(* LS Electric XG5000 project: test *)
(* PLC NewPLC *)
(* module base 0 slot 3: Output Module:XBE-TN/TP32A (Transistor Output, 32 Contacts (0.2A, Sink Output/Source Output)) *)

PROGRAM forvup (* task: Scan Program *)
VAR
    dummy : DWORD;
    fromvup AT D01006 : DWORD;
    mysign1 AT D01000 : DWORD;
    mysign2 AT D01002 : DWORD;
    tovup AT D01004 : DWORD;
    _p100 AT P00100 : BIT;
    _p101 AT P00101 : BIT;
    _p102 AT P00102 : BIT;
    _p103 AT P00103 : BIT;
    _p104 AT P00104 : BIT;
    _p105 AT P00105 : BIT;
    _p106 AT P00106 : BIT;
    _p107 AT P00107 : BIT;
    _p108 AT P00108 : BIT;
    _p109 AT P00109 : BIT;
    _p110 AT P00110 : BIT;
    _p111 AT P00111 : BIT;
    _p120 AT P00120 : BIT;
    _p121 AT P00121 : BIT;
    _p122 AT P00122 : BIT;
    _p123 AT P00123 : BIT;
    _p124 AT P00124 : BIT;
    _p125 AT P00125 : BIT;
    _p126 AT P00126 : BIT;
    _p127 AT P00127 : BIT;
    _p128 AT P00128 : BIT;
    _p129 AT P00129 : BIT;
    _p130 AT P00130 : BIT;
    _p131 AT P00131 : BIT;
    _p132 AT P00132 : BIT;
    _p133 AT P00133 : BIT;
    _p134 AT P00134 : BIT;
    _p135 AT P00135 : BIT;
    _p136 AT P00136 : BIT;
    _p137 AT P00137 : BIT;
    _p138 AT P00138 : BIT;
    _p139 AT P00139 : BIT;
    _p140 AT P00140 : BIT;
    _p141 AT P00141 : BIT;
    _p142 AT P00142 : BIT;
    _p143 AT P00143 : BIT;
    _p144 AT P00144 : BIT;
    _p145 AT P00145 : BIT;
    _p146 AT P00146 : BIT;
    _p147 AT P00147 : BIT;
    _p148 AT P00148 : BIT;
    _p149 AT P00149 : BIT;
    _p150 AT P00150 : BIT;
    _p151 AT P00151 : BIT;
    _p80 AT P00080 : BIT;
    _p81 AT P00081 : BIT;
    _p82 AT P00082 : BIT;
    _p83 AT P00083 : BIT;
    _p84 AT P00084 : BIT;
    _p85 AT P00085 : BIT;
    _p86 AT P00086 : BIT;
    _p87 AT P00087 : BIT;
    _p88 AT P00088 : BIT;
    _p89 AT P00089 : BIT;
    _p90 AT P00090 : BIT;
    _p91 AT P00091 : BIT;
    _p92 AT P00092 : BIT;
    _p93 AT P00093 : BIT;
    _p94 AT P00094 : BIT;
    _p95 AT P00095 : BIT;
    _p96 AT P00096 : BIT;
    _p97 AT P00097 : BIT;
    _p98 AT P00098 : BIT;
    _p99 AT P00099 : BIT;
END_VAR
(* sign *)
mysign1:=1380534594;
mysign2:=1432778632;
(* copy from vup to XGSIM inputs*)
IF (fromvup AND 1) =0 THEN
_p80:=FALSE;	
ELSE
_p80:=TRUE;	
END_IF;
IF (fromvup AND 2) =0 THEN
_p81:=FALSE;	
ELSE
_p81:=TRUE;	
END_IF;
IF (fromvup AND 4) =0 THEN
_p82:=FALSE;	
ELSE
_p82:=TRUE;	
END_IF;
IF (fromvup AND 8) =0 THEN
_p83:=FALSE;	
ELSE
_p83:=TRUE;	
END_IF;
IF (fromvup AND H10) =0 THEN
_p84:=FALSE;	
ELSE
_p84:=TRUE;	
END_IF;
IF (fromvup AND H20) =0 THEN
_p85:=FALSE;	
ELSE
_p85:=TRUE;	
END_IF;
IF (fromvup AND H40) =0 THEN
_p86:=FALSE;	
ELSE
_p86:=TRUE;	
END_IF;
IF (fromvup AND H80) =0 THEN
_p87:=FALSE;	
ELSE
_p87:=TRUE;	
END_IF;
IF (fromvup AND H100) =0 THEN
_p88:=FALSE;	
ELSE
_p88:=TRUE;	
END_IF;
IF (fromvup AND H200) =0 THEN
_p89:=FALSE;	
ELSE
_p89:=TRUE;	
END_IF;
IF (fromvup AND H400) =0 THEN
_p90:=FALSE;	
ELSE
_p90:=TRUE;	
END_IF;
IF (fromvup AND H800) =0 THEN
_p91:=FALSE;	
ELSE
_p91:=TRUE;	
END_IF;
IF (fromvup AND H1000) =0 THEN
_p92:=FALSE;	
ELSE
_p92:=TRUE;	
END_IF;
IF (fromvup AND H2000) =0 THEN
_p93:=FALSE;	
ELSE
_p93:=TRUE;	
END_IF;
IF (fromvup AND H4000) =0 THEN
_p94:=FALSE;	
ELSE
_p94:=TRUE;	
END_IF;
IF (fromvup AND H8000) =0 THEN
_p95:=FALSE;	
ELSE
_p95:=TRUE;	
END_IF;
IF (fromvup AND H10000) =0 THEN
_p96:=FALSE;	
ELSE
_p96:=TRUE;	
END_IF;
IF (fromvup AND H20000) =0 THEN
_p97:=FALSE;	
ELSE
_p97:=TRUE;	
END_IF;
IF (fromvup AND H40000) =0 THEN
_p98:=FALSE;	
ELSE
_p98:=TRUE;	
END_IF;
IF (fromvup AND H80000) =0 THEN
_p99:=FALSE;	
ELSE
_p99:=TRUE;	
END_IF;
IF (fromvup AND H100000) =0 THEN
_p100:=FALSE;	
ELSE
_p100:=TRUE;	
END_IF;
IF (fromvup AND H200000) =0 THEN
_p101:=FALSE;	
ELSE
_p101:=TRUE;	
END_IF;
IF (fromvup AND H400000) =0 THEN
_p102:=FALSE;	
ELSE
_p102:=TRUE;	
END_IF;
IF (fromvup AND H800000) =0 THEN
_p103:=FALSE;	
ELSE
_p103:=TRUE;	
END_IF;
IF (fromvup AND H1000000) =0 THEN
_p104:=FALSE;	
ELSE
_p104:=TRUE;	
END_IF;
IF (fromvup AND H2000000) =0 THEN
_p105:=FALSE;	
ELSE
_p105:=TRUE;	
END_IF;
IF (fromvup AND H4000000) =0 THEN
_p106:=FALSE;	
ELSE
_p106:=TRUE;	
END_IF;
IF (fromvup AND H8000000) =0 THEN
_p107:=FALSE;	
ELSE
_p107:=TRUE;	
END_IF;
IF (fromvup AND H10000000) =0 THEN
_p108:=FALSE;	
ELSE
_p108:=TRUE;	
END_IF;
IF (fromvup AND H20000000) =0 THEN
_p109:=FALSE;	
ELSE
_p109:=TRUE;	
END_IF;
IF (fromvup AND H40000000) =0 THEN
_p110:=FALSE;	
ELSE
_p110:=TRUE;	
END_IF;
IF (fromvup AND H80000000) =0 THEN
_p111:=FALSE;	
ELSE
_p111:=TRUE;	
END_IF;


(* copy XGSIM outputs to vup)
dummy:=0;
IF _p120 THEN
	dummy:=dummy OR 1;
END_IF;
IF _p121 THEN
	dummy:=dummy OR 2;
END_IF;
IF _p122 THEN
	dummy:=dummy OR 4;
END_IF;
IF _p123 THEN
	dummy:=dummy OR 8;
END_IF;
IF _p124 THEN
	dummy:=dummy OR H10;
END_IF;
IF _p125 THEN
	dummy:=dummy OR H20;
END_IF;
IF _p126 THEN
	dummy:=dummy OR H40;
END_IF;
IF _p127 THEN
	dummy:=dummy OR H80;
END_IF;
IF _p128 THEN
	dummy:=dummy OR H100;
END_IF;
IF _p129 THEN
	dummy:=dummy OR H200;
END_IF;
IF _p130 THEN
	dummy:=dummy OR H400;
END_IF;
IF _p131 THEN
	dummy:=dummy OR H800;
END_IF;
IF _p132 THEN
	dummy:=dummy OR H1000;
END_IF;
IF _p133 THEN
	dummy:=dummy OR H2000;
END_IF;
IF _p134 THEN
	dummy:=dummy OR H4000;
END_IF;
IF _p135 THEN
	dummy:=dummy OR H8000;
END_IF;
IF _p136 THEN
	dummy:=dummy OR H10000;
END_IF;
IF _p137 THEN
	dummy:=dummy OR H20000;
END_IF;
IF _p138 THEN
	dummy:=dummy OR H40000;
END_IF;
IF _p139 THEN
	dummy:=dummy OR H80000;
END_IF;
IF _p140 THEN
	dummy:=dummy OR H100000;
END_IF;
IF _p141 THEN
	dummy:=dummy OR H200000;
END_IF;
IF _p142 THEN
	dummy:=dummy OR H400000;
END_IF;
IF _p143 THEN
	dummy:=dummy OR H800000;
END_IF;
IF _p144 THEN
	dummy:=dummy OR H1000000;
END_IF;
IF _p145 THEN
	dummy:=dummy OR H2000000;
END_IF;
IF _p146 THEN
	dummy:=dummy OR H4000000;
END_IF;
IF _p147 THEN
	dummy:=dummy OR H8000000;
END_IF;
IF _p148 THEN
	dummy:=dummy OR H10000000;
END_IF;
IF _p149 THEN
	dummy:=dummy OR H20000000;
END_IF;
IF _p150 THEN
	dummy:=dummy OR H40000000;
END_IF;
IF _p151 THEN
	dummy:=dummy OR H80000000;
END_IF;



tovup:=dummy;
END_PROGRAM

PROGRAM main (* task: Scan Program *)
VAR
    myi0 AT P00080 : BIT;
    myq0 AT P00120 : BIT;
END_VAR

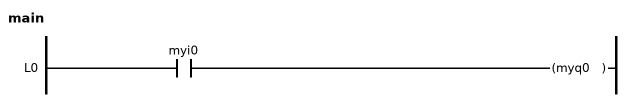
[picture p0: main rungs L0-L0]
; L0
LOAD      myi0
OUT       myq0
END_PROGRAM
